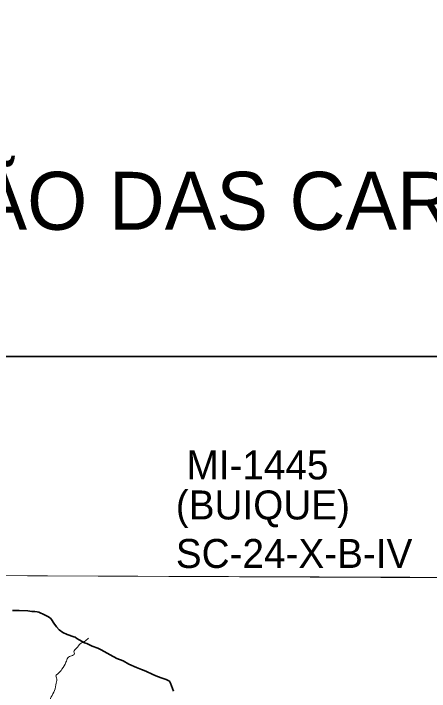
# Model space of a CAD drawing. Extents: x -1643653 to 4543381, y 1624270 to 13878484.
# Drawn here: x 597627 to 604813, y 8918990 to 8930690 of the extents above; entities that cross this region are included whole.
import ezdxf
from ezdxf.enums import TextEntityAlignment as Align

# ---------------------------------------------------------------- set-up
doc = ezdxf.new("R2010")
doc.units = 0
doc.header["$LTSCALE"] = 200
doc.linetypes.add('LONG_DASH_SHORT_DASH', pattern=[9.9, 6, -1.2, 1.5, -1.2])
doc.layers.add('6', color=7, linetype='Continuous', lineweight=13)
doc.layers.add('60', color=7, linetype='Continuous', lineweight=13)

msp = doc.modelspace()

# ---------------------------------------------------------------- linework, layer by layer
at = {"layer": '6', "lineweight": 35}
msp.add_lwpolyline([(574695.3, 8924769.6), (626625.7, 8924769.6), (626625.7, 8896026.7), (574695.3, 8896026.7)], close=True, dxfattribs=at)
at = {"layer": '6'}
msp.add_lwpolyline([(574684.9, 8921064.7), (596639.8, 8920989.8), (607636.3, 8920937.2), (626625.7, 8920820.5)], dxfattribs=at)
msp.add_lwpolyline([(607600.8, 8920952.4), (596639.8, 8920989.8), (596608.8, 8909934.4), (607569.8, 8909894.9)], close=True, dxfattribs=at)
at = {"layer": '6', "linetype": 'LONG_DASH_SHORT_DASH', "lineweight": 35}
msp.add_lwpolyline([(597610.2, 8920386.4), (597650.2, 8920385.4), (597721.8, 8920389.3), (597874.1, 8920380.3), (597945, 8920371.9), (597993.4, 8920372.2), (598032.7, 8920365.4), (598064.9, 8920356.1), (598162, 8920314.6), (598221.7, 8920285.1), (598264.7, 8920254.4), (598285.8, 8920233.5), (598324.6, 8920168.7), (598370.5, 8920103.8), (598416.6, 8920052.4), (598480.7, 8920006.1), (598552.1, 8919975.8), (598671.1, 8919931.5), (598692.3, 8919924.3), (598721.8, 8919905.9), (598759.1, 8919882.4), (598851.5, 8919831.9), (598891.4, 8919816.1), (598987.2, 8919772.7), (599084.4, 8919739.6), (599142.2, 8919708.2), (599298.2, 8919621.7), (599412.6, 8919560.7), (599519.3, 8919519.8), (599620.2, 8919462.1), (599750.1, 8919406.2), (599835.6, 8919368), (599912.8, 8919340.3), (600036.8, 8919285), (600114.6, 8919250.2), (600193.7, 8919219.8), (600262.6, 8919196), (600311.4, 8919174.3), (600323, 8919165.1), (600340.1, 8919135.3), (600389.9, 8918996.8)], dxfattribs=at)
at = {"layer": '6'}
msp.add_spline([(598300.5, 8917392.3), (598315.3, 8917441.1), (598255.3, 8917504.1), (598239.6, 8917592.4), (598271.1, 8917724.9), (598331, 8917860.5), (598362.6, 8917945.7), (598337.3, 8918008.8), (598271.1, 8918059.2), (598264.8, 8918122.3), (598283.7, 8918169.6), (598293.2, 8918216.9), (598258.5, 8918251.6), (598220.6, 8918330.5), (598230.1, 8918494.5), (598230.1, 8918586), (598223.8, 8918652.2), (598198.6, 8918705.8), (598223.8, 8918775.2), (598277.4, 8918895.6), (598337.3, 8919006), (598365.7, 8919135.4), (598368.9, 8919223.8), (598359.4, 8919260.4), (598397.3, 8919298.2), (598463.5, 8919374), (598532.9, 8919493.9), (598564.4, 8919569.6), (598630.7, 8919607.5), (598678, 8919639.1), (598668.5, 8919676.9), (598715.8, 8919736.9), (598775.8, 8919809.5), (598854.6, 8919853.7), (598920.8, 8919907.3)], degree=3, dxfattribs=at)
at = {"layer": '60', "lineweight": 25}
msp.add_spline([(814781, 9009175.5), (814787.2, 9009173.4), (814796.9, 9009173.4), (814799.4, 9009172.4), (814805.1, 9009174.5), (814805.6, 9009176.5), (814811.7, 9009179.5), (814811.7, 9009179.5), (814801.5, 9009181), (814790.7, 9009181.5), (814784.1, 9009183.1), (814777.4, 9009185.1), (814778.4, 9009175.5)], degree=3, dxfattribs=at)

# ---------------------------------------------------------------- texts
at = {"layer": '6'}
msp.add_text('ARTICULAÇÃO DAS CARTAS 1:100.000', height=1000, dxfattribs=at).set_placement((601765.5, 8926958.2), align=Align.CENTER)
for s, p in [('MI-1445', (600615.8, 8922649.4)), ('(BUIQUE)', (600431.4, 8921958.8)), ('SC-24-X-B-IV', (600431.4, 8921121.7))]:
    msp.add_text(s, height=500, dxfattribs=at).set_placement(p)

doc.saveas('drawing.dxf')
